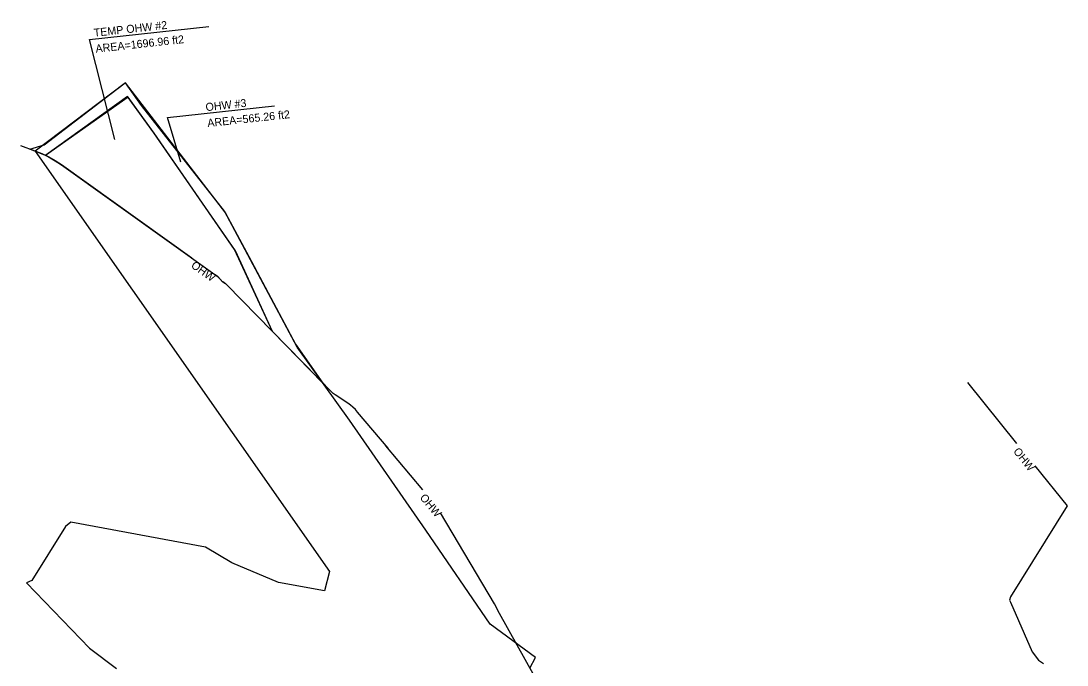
# Model space of a CAD drawing. Extents: x 1509537 to 1510685, y 401169 to 402194.
# Drawn here: x 1509536.8 to 1509902.6, y 401968.9 to 402194.1 of the extents above; entities that cross this region are included whole.
import ezdxf

# ---------------------------------------------------------------- set-up
doc = ezdxf.new("R2010")
doc.units = 0
for name, color, linetype in [('LAWE', 7, 'Continuous'), ('LAWE_P', 7, 'Continuous'), ('LAWE_P_T', 7, 'Continuous'), ('Level 6', 7, 'Continuous'), ('Level 9', 7, 'Continuous')]:
    doc.layers.add(name, color=color, linetype=linetype)

msp = doc.modelspace()

# ---------------------------------------------------------------- linework, layer by layer
at = {"layer": 'LAWE'}
for points in [[(1509596.49, 402111.19), (1509550.96, 402143.76), (1509548.77, 402145.22), (1509546.5, 402146.51), (1509544.15, 402147.65), (1509541.71, 402148.62), (1509536.75, 402150.41)], [(1509665.14, 402044.69), (1509654.52, 402057.36), (1509653.73, 402058.22), (1509652.89, 402059.03), (1509652, 402059.76), (1509651.05, 402060.44), (1509646.63, 402063.32), (1509645.91, 402063.83), (1509608.69, 402101.91), (1509608.54, 402102.06), (1509608.39, 402102.19), (1509608.23, 402102.32), (1509608.06, 402102.43), (1509607.36, 402102.88), (1509607.19, 402103), (1509607.04, 402103.13), (1509606.89, 402103.27), (1509606.75, 402103.42), (1509606.08, 402104.2), (1509605.92, 402104.37), (1509605.75, 402104.54), (1509605.57, 402104.69), (1509605.38, 402104.84), (1509604.73, 402105.3)], [(1509867.86, 402067.71), (1509884.96, 402046.37)], [(1509677.31, 402030.18), (1509664.43, 402045.53)], [(1509891.32, 402038.5), (1509902.63, 402024.52), (1509882.89, 401992.68), (1509882.46, 401991.62), (1509882.63, 401991.29), (1509882.8, 401990.9), (1509890.43, 401973.52), (1509892.64, 401970.54), (1509894.37, 401969.45)], [(1509733.33, 401940.36), (1509716.46, 401964.75), (1509704.07, 401986.85), (1509702.4, 401990.32), (1509683.49, 402022.15)]]:
    msp.add_lwpolyline(points, dxfattribs=at)
at = {"layer": 'LAWE_P'}
for p, q in [((1509545.34, 402147.07), (1509539.87, 402149.28)), ((1509632.77, 402081.09), (1509642.34, 402067.48))]:
    msp.add_line(p, q, dxfattribs=at)
for points in [[(1509539.87, 402149.28), (1509544.83, 402150.73), (1509567.81, 402168.43), (1509573.21, 402172.42), (1509608.29, 402126.94), (1509616.46, 402111.7), (1509632.77, 402081.09)], [(1509642.34, 402067.48), (1509624.71, 402085.52), (1509611.43, 402114.15), (1509583.37, 402154.83), (1509574.2, 402167.44), (1509545.34, 402147.07)], [(1509642.34, 402067.48), (1509624.71, 402085.52)]]:
    msp.add_lwpolyline(points, dxfattribs=at)
at = {"layer": 'LAWE_P_T'}
for points in [[(1509569.59, 402152.65), (1509560.7, 402187.63), (1509602.47, 402192.19)], [(1509592.66, 402144.74), (1509588.02, 402160.34), (1509625.48, 402164.42)]]:
    msp.add_lwpolyline(points, dxfattribs=at)
at = {"layer": 'Level 6'}
for points in [[(1509624.71, 402085.52), (1509611.74, 402113.71), (1509583.25, 402155.01), (1509574.03, 402167.67), (1509545.42, 402147.13)], [(1509545.42, 402147.13), (1509548.77, 402145.22), (1509550.96, 402143.76), (1509605.38, 402104.84), (1509605.57, 402104.69), (1509605.75, 402104.54), (1509605.92, 402104.37), (1509606.08, 402104.2), (1509606.75, 402103.42), (1509606.89, 402103.27), (1509607.04, 402103.13), (1509607.19, 402103), (1509607.36, 402102.88), (1509608.06, 402102.43), (1509608.23, 402102.32), (1509608.39, 402102.19), (1509608.54, 402102.06), (1509608.69, 402101.91), (1509624.71, 402085.52)]]:
    msp.add_lwpolyline(points, dxfattribs=at)
at = {"layer": 'Level 9'}
for p, q in [((1509554.21, 402018.88), (1509552.36, 402017.38)), ((1509552.36, 402017.38), (1509540.54, 401998.41)), ((1509540.54, 401998.41), (1509538.65, 401997.63)), ((1509560.78, 401974.8), (1509570.18, 401967.69)), ((1509714.74, 401967.81), (1509716.67, 401971.54))]:
    msp.add_line(p, q, dxfattribs=at)
for points in [[(1509716.67, 401971.54), (1509700.83, 401983.19), (1509678.39, 402016.08), (1509651.62, 402054.55), (1509633.35, 402080), (1509607.94, 402127.61), (1509578.91, 402164.59), (1509573.33, 402172.52), (1509541.71, 402148.62), (1509644.71, 402001.61), (1509642.89, 401994.81), (1509626.83, 401997.75), (1509610.5, 402004.57), (1509601.36, 402010.05), (1509554.21, 402018.88)], [(1509538.65, 401997.63), (1509560.78, 401974.8)]]:
    msp.add_lwpolyline(points, dxfattribs=at)

# ---------------------------------------------------------------- texts
at = {"layer": 'LAWE'}
for rotation, p in [(324.4231, (1509596, 402108.1)), (308.7051, (1509883.65, 402043.53)), (309.9885, (1509676.07, 402027.31))]:
    msp.add_text('OHW', height=2.8, rotation=rotation, dxfattribs=at).set_placement(p)
at = {"layer": 'LAWE_P_T'}
for s, p in [('TEMP OHW #2', (1509562.38, 402188.56)), ('AREA=1696.96 ft2', (1509562.99, 402183)), ('OHW #3', (1509601.48, 402162.55)), ('AREA=565.26 ft2', (1509602.09, 402156.99))]:
    msp.add_text(s, height=2.8, rotation=6.2219, dxfattribs=at).set_placement(p)

doc.saveas('drawing.dxf')
